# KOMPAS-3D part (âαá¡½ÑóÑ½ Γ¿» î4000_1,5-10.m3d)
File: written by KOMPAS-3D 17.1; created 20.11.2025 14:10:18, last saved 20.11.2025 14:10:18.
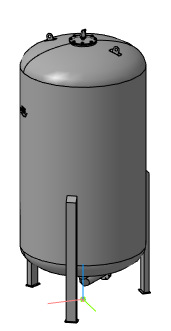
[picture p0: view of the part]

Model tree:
1. Операция без истории:1

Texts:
  REVIT MATERIAL OVERRIDDEN
  REVIT MATERIAL ID
  REVIT SUBCATEGORY ID
  REVIT CATEGORY ID
  REVIT ELEMENT ID
  REVIT BREP TAG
